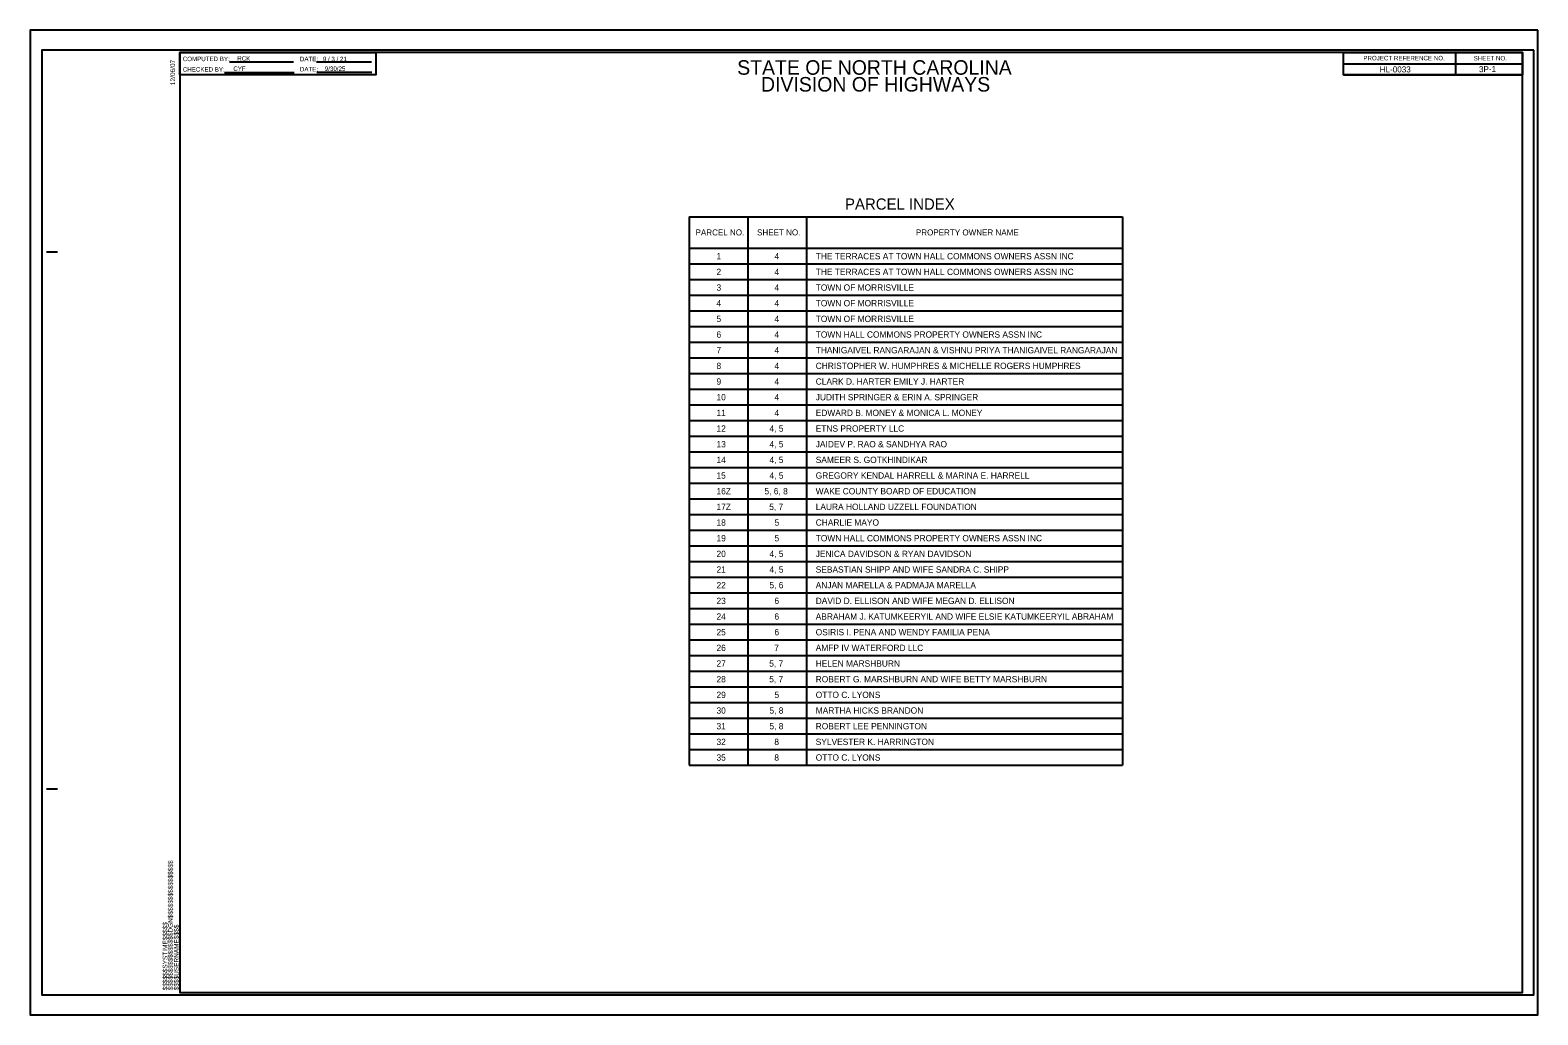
# Model space of a CAD drawing. Extents: x 1757307 to 1758991, y 635385 to 636485.
import ezdxf

# ---------------------------------------------------------------- set-up
doc = ezdxf.new("R2010")
doc.units = 0
for name, color, linetype in [('Sheet Cutting Line CELL', 7, 'Continuous'), ('Sheet Data Field CELL', 7, 'Continuous'), ('Sheet Plot Border Inside CELL', 7, 'Continuous'), ('Sheet Plot Border Outside CELL', 7, 'Continuous'), ('Sheet Summary Combination CELL', 7, 'Continuous'), ('Sheet Summary Combination Grid CELL', 7, 'Continuous')]:
    doc.layers.add(name, color=color, linetype=linetype)

msp = doc.modelspace()

# ---------------------------------------------------------------- linework, layer by layer
at = {"layer": 'Sheet Cutting Line CELL'}
for p, q in [((1758990.7, 636484.5), (1757306.7, 636484.5)), ((1757306.7, 636484.5), (1757306.7, 635384.5)), ((1757306.7, 635384.5), (1758990.7, 635384.5))]:
    msp.add_line(p, q, dxfattribs=at)
at = {"layer": 'Sheet Plot Border Inside CELL'}
msp.add_lwpolyline([(1758986.2, 636462.1), (1757319.7, 636462.1), (1757319.7, 635407), (1758986.2, 635407)], close=True, dxfattribs=at)
at = {"layer": 'Sheet Plot Border Outside CELL'}
msp.add_lwpolyline([(1758990.7, 636484.5), (1757306.7, 636484.5), (1757306.7, 635384.5), (1758990.7, 635384.5)], close=True, dxfattribs=at)
at = {"layer": 'Sheet Summary Combination CELL'}
for p, q in [((1758898.7, 636459.5), (1758898.7, 636434.5)), ((1757523.9, 636437.4), (1757601.6, 636437.4)), ((1757529.3, 636449.1), (1757600.9, 636449.1)), ((1757626.7, 636449), (1757688.1, 636449)), ((1757626.8, 636437.5), (1757688.2, 636437.5)), ((1758773.6, 636447), (1758973.7, 636447)), ((1758773.6, 636434.5), (1758973.7, 636434.5)), ((1758207.6, 636276), (1758207.6, 636276)), ((1758216.3, 636275.8), (1758216.3, 636275.8)), ((1758229, 636276.1), (1758229, 636276.1)), ((1758236.8, 636276), (1758236.8, 636276)), ((1757324.8, 636237), (1757337.3, 636237)), ((1757324.8, 635637), (1757337.3, 635637)), ((1757473.7, 635484.5), (1757473.7, 635484.5))]:
    msp.add_line(p, q, dxfattribs=at)
for points in [[(1758973.7, 636459.5), (1757473.7, 636459.5), (1757473.7, 635409.5), (1758973.7, 635409.5)], [(1757473.7, 636459.5), (1757692.7, 636459.5), (1757692.7, 636434.5), (1757473.7, 636434.5)], [(1758773.6, 636459.5), (1758973.7, 636459.5), (1758973.7, 636434.5), (1758773.6, 636434.5)]]:
    msp.add_lwpolyline(points, close=True, dxfattribs=at)
at = {"layer": 'Sheet Summary Combination Grid CELL'}
for p, q in [((1758042.7, 636276), (1758526.7, 636276)), ((1758042.7, 636276), (1758042.7, 635663.5)), ((1758108.3, 636276), (1758108.3, 635663.5)), ((1758174, 636276), (1758174, 635663.5)), ((1758526.7, 636276), (1758526.7, 635663.5)), ((1758042.7, 636241), (1758526.7, 636241)), ((1758042.7, 636223.5), (1758526.7, 636223.5)), ((1758042.7, 636206), (1758526.7, 636206)), ((1758042.7, 636188.5), (1758526.7, 636188.5)), ((1758042.7, 636188.5), (1758526.7, 636188.5)), ((1758042.7, 636171), (1758526.7, 636171)), ((1758042.7, 636153.5), (1758526.7, 636153.5)), ((1758042.7, 636136), (1758526.7, 636136)), ((1758042.7, 636118.5), (1758526.7, 636118.5)), ((1758042.7, 636101), (1758526.7, 636101)), ((1758042.7, 636083.5), (1758526.7, 636083.5)), ((1758042.7, 636066), (1758526.7, 636066)), ((1758042.7, 636048.5), (1758526.7, 636048.5)), ((1758042.7, 636031), (1758526.7, 636031)), ((1758042.7, 636013.5), (1758526.7, 636013.5)), ((1758042.7, 635996), (1758526.7, 635996)), ((1758042.7, 635978.5), (1758526.7, 635978.5)), ((1758042.7, 635978.5), (1758526.7, 635978.5)), ((1758042.7, 635961), (1758526.7, 635961)), ((1758042.7, 635943.5), (1758526.7, 635943.5)), ((1758042.7, 635926), (1758526.7, 635926)), ((1758042.7, 635908.5), (1758526.7, 635908.5)), ((1758042.7, 635891), (1758526.7, 635891)), ((1758042.7, 635873.5), (1758526.7, 635873.5)), ((1758042.7, 635856), (1758526.7, 635856)), ((1758042.7, 635838.5), (1758526.7, 635838.5)), ((1758042.7, 635821), (1758526.7, 635821)), ((1758042.7, 635803.5), (1758526.7, 635803.5)), ((1758042.7, 635786), (1758526.7, 635786)), ((1758042.7, 635768.5), (1758526.7, 635768.5)), ((1758042.7, 635768.5), (1758526.7, 635768.5)), ((1758042.7, 635751), (1758526.7, 635751)), ((1758042.7, 635733.5), (1758526.7, 635733.5)), ((1758042.7, 635716), (1758526.7, 635716)), ((1758042.7, 635698.5), (1758526.7, 635698.5)), ((1758042.7, 635681), (1758526.7, 635681)), ((1758042.7, 635663.5), (1758526.7, 635663.5)), ((1758042.7, 635663.5), (1758526.7, 635663.5)), ((1758042.7, 635663.5), (1758526.7, 635663.5))]:
    msp.add_line(p, q, dxfattribs=at)

# ---------------------------------------------------------------- texts
at = {"layer": 'Sheet Data Field CELL'}
for s, p in [('HL-0033', (1758814.1, 636437.3)), ('3P-1', (1758924.9, 636437.6))]:
    msp.add_text(s, height=6.75, dxfattribs=at).set_placement(p)
at = {"layer": 'Sheet Summary Combination CELL'}
for s, height, p in [('COMPUTED BY:', 5, (1757477.1, 636449.9)), ('RCK', 5, (1757538, 636450.3)), ('DATE:', 5, (1757608, 636449.8)), ('9 / 3 / 21', 5, (1757633.6, 636449.8)), ('STATE OF NORTH CAROLINA', 16.25, (1758096.4, 636434.7)), ('PROJECT REFERENCE NO.', 5, (1758795.8, 636450.8)), ('SHEET NO.', 5, (1758919, 636450.7)), ('CHECKED BY:', 5, (1757477.2, 636438.2)), ('CYF', 5, (1757533.6, 636439)), ('DATE:', 5, (1757608, 636438.4)), ('9/30/25', 5, (1757635.8, 636439)), ('DIVISION OF HIGHWAYS', 16.25, (1758123, 636415.9)), ('PARCEL NO.', 6.72, (1758049.9, 636255.2)), ('SHEET NO.', 6.72, (1758118.6, 636255.2)), ('PROPERTY OWNER NAME', 6.72, (1758296, 636255.2)), ('1', 7, (1758073.3, 636228.5)), ('4', 7, (1758138.1, 636228.5)), ('THE TERRACES AT TOWN HALL COMMONS OWNERS ASSN INC', 7, (1758184.1, 636228.5)), ('2', 7, (1758073.3, 636211)), ('4', 7, (1758138.1, 636211)), ('THE TERRACES AT TOWN HALL COMMONS OWNERS ASSN INC', 7, (1758184.1, 636211)), ('3', 7, (1758073.3, 636193.5)), ('4', 7, (1758138.1, 636193.5)), ('TOWN OF MORRISVILLE', 7, (1758184.1, 636193.5)), ('4', 7, (1758073.3, 636176)), ('4', 7, (1758138.1, 636176)), ('TOWN OF MORRISVILLE', 7, (1758184.1, 636176)), ('5', 7, (1758073.3, 636158.5)), ('4', 7, (1758138.1, 636158.5)), ('TOWN OF MORRISVILLE', 7, (1758184.1, 636158.5)), ('6', 7, (1758073.3, 636141)), ('4', 7, (1758138.1, 636141)), ('TOWN HALL COMMONS PROPERTY OWNERS ASSN INC', 7, (1758184.1, 636141)), ('7', 7, (1758073.3, 636123.5)), ('4', 7, (1758138.1, 636123.5)), ('THANIGAIVEL RANGARAJAN & VISHNU PRIYA THANIGAIVEL RANGARAJAN', 7, (1758184.1, 636123.5)), ('8', 7, (1758073.3, 636106)), ('4', 7, (1758138.1, 636106)), ('CHRISTOPHER W. HUMPHRES & MICHELLE ROGERS HUMPHRES', 7, (1758184.1, 636106)), ('9', 7, (1758073.3, 636088.5)), ('4', 7, (1758138.1, 636088.5)), ('CLARK D. HARTER EMILY J. HARTER', 7, (1758184.1, 636088.5)), ('10', 7, (1758073.3, 636071)), ('4', 7, (1758138.1, 636071)), ('JUDITH SPRINGER & ERIN A. SPRINGER', 7, (1758184.1, 636071)), ('11', 7, (1758073.3, 636053.5)), ('4', 7, (1758138.1, 636053.5)), ('EDWARD B. MONEY & MONICA L. MONEY', 7, (1758184.1, 636053.5)), ('12', 7, (1758073.3, 636036)), ('4, 5', 7, (1758132.5, 636036)), ('ETNS PROPERTY LLC', 7, (1758184.1, 636036)), ('13', 7, (1758073.3, 636018.5)), ('4, 5', 7, (1758132.5, 636018.5)), ('JAIDEV P. RAO & SANDHYA RAO', 7, (1758184.1, 636018.5)), ('14', 7, (1758073.3, 636001)), ('4, 5', 7, (1758132.5, 636001)), ('SAMEER S. GOTKHINDIKAR', 7, (1758184.1, 636001)), ('15', 7, (1758073.3, 635983.5)), ('4, 5', 7, (1758132.5, 635983.5)), ('GREGORY KENDAL HARRELL & MARINA E. HARRELL', 7, (1758184.1, 635983.5)), ('16Z', 7, (1758073.3, 635966)), ('5, 6, 8', 7, (1758126.9, 635966)), ('WAKE COUNTY BOARD OF EDUCATION', 7, (1758184.1, 635966)), ('17Z', 7, (1758073.3, 635948.5)), ('5, 7', 7, (1758132.2, 635948.5)), ('LAURA HOLLAND UZZELL FOUNDATION', 7, (1758184.1, 635948.5)), ('18', 7, (1758073.3, 635931)), ('5', 7, (1758138.1, 635931)), ('CHARLIE MAYO', 7, (1758184.1, 635931)), ('19', 7, (1758073.3, 635913.5)), ('5', 7, (1758138.1, 635913.5)), ('TOWN HALL COMMONS PROPERTY OWNERS ASSN INC', 7, (1758184.1, 635913.5)), ('20', 7, (1758073.3, 635896)), ('4, 5', 7, (1758132.5, 635896)), ('JENICA DAVIDSON & RYAN DAVIDSON', 7, (1758184.1, 635896)), ('21', 7, (1758073.3, 635878.5)), ('4, 5', 7, (1758132.5, 635878.5)), ('SEBASTIAN SHIPP AND WIFE SANDRA C. SHIPP', 7, (1758184.1, 635878.5)), ('22', 7, (1758073.3, 635861)), ('5, 6', 7, (1758132.4, 635861)), ('ANJAN MARELLA & PADMAJA MARELLA', 7, (1758184.1, 635861)), ('23', 7, (1758073.3, 635843.5)), ('6', 7, (1758138, 635843.5)), ('DAVID D. ELLISON AND WIFE MEGAN D. ELLISON', 7, (1758184.1, 635843.5)), ('24', 7, (1758073.3, 635826)), ('6', 7, (1758138, 635826)), ('ABRAHAM J. KATUMKEERYIL AND WIFE ELSIE KATUMKEERYIL ABRAHAM', 7, (1758184.1, 635826)), ('25', 7, (1758073.3, 635808.5)), ('6', 7, (1758138, 635808.5)), ('OSIRIS I. PENA AND WENDY FAMILIA PENA', 7, (1758184.1, 635808.5)), ('26', 7, (1758073.3, 635791)), ('7', 7, (1758137.8, 635791)), ('AMFP IV WATERFORD LLC', 7, (1758184.1, 635791)), ('27', 7, (1758073.3, 635773.5)), ('5, 7', 7, (1758132.2, 635773.5)), ('HELEN MARSHBURN', 7, (1758184.1, 635773.5)), ('28', 7, (1758073.3, 635756)), ('5, 7', 7, (1758132.2, 635756)), ('ROBERT G. MARSHBURN AND WIFE BETTY MARSHBURN', 7, (1758184.1, 635756)), ('29', 7, (1758073.3, 635738.5)), ('5', 7, (1758138.1, 635738.5)), ('OTTO C. LYONS', 7, (1758184.1, 635738.5)), ('30', 7, (1758073.3, 635721)), ('5, 8', 7, (1758132.4, 635721)), ('MARTHA HICKS BRANDON', 7, (1758184.1, 635721)), ('31', 7, (1758073.3, 635703.5)), ('5, 8', 7, (1758132.4, 635703.5)), ('ROBERT LEE PENNINGTON', 7, (1758184.1, 635703.5)), ('32', 7, (1758073.3, 635686)), ('8', 7, (1758137.9, 635686)), ('SYLVESTER K. HARRINGTON', 7, (1758184.1, 635686)), ('35', 7, (1758073.3, 635668.5)), ('8', 7, (1758137.9, 635668.5)), ('OTTO C. LYONS', 7, (1758184.1, 635668.5))]:
    msp.add_text(s, height=height, dxfattribs=at).set_placement(p)
for s, height, rotation, p in [('12/06/07', 5.25, 90, (1757468.5, 636423.1)), ('PARCEL INDEX', 12.5, 0.0119, (1758216.8, 636284)), ('$$$$$$$$$$$$$$$$DGN$$$$$$$$$$$$$$$$', 5.25, 90, (1757466, 635411.9)), ('$$$$$$SYSTIME$$$$$', 5.25, 90, (1757460, 635411.9)), ('$$$$USERNAME$$$$', 5.25, 90, (1757472.6, 635411.9))]:
    msp.add_text(s, height=height, rotation=rotation, dxfattribs=at).set_placement(p)

doc.saveas('drawing.dxf')
